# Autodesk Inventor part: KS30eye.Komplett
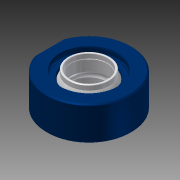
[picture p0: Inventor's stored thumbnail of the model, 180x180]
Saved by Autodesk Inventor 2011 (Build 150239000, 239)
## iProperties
Created: 2010-10
Part Number: KS30eye.Komplett
Document SubType Name: Modeling
Designer: tribel
Density: 1 g/cm^3
Author: tribel
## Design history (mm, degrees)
derived "KS30eye.iam"
body "Solid1"
sketch "Part6.ipt:1"
sketch "Part12.ipt:1"
sketch "Part14.ipt:1"
sketch "Smørenippel.ipt:1"
workaxis "Work Axis2"
